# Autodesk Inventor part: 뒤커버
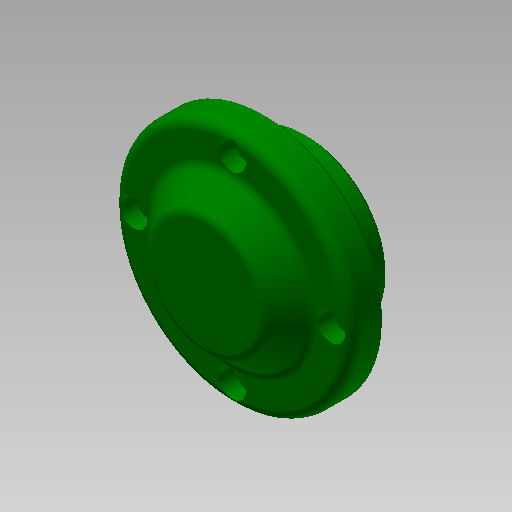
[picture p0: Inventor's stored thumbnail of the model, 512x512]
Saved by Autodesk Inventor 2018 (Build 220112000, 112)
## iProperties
Created: 2017-08
Part Number: 뒤커버
Material: 알루미늄 6061
Document SubType Name: Modeling
Designer: mduedu
Density: 2.71 g/cm^3
Appearance: 알루미늄 - 평지
Author: mduedu
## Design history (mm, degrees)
sketch "스케치1"
  geometry: C1 r 35 at (0, 0); 1 further point
  constraints: 1 centre point, 1 coincident
  dimensions: "d0" = 70 diameter of C1
extrude "돌출1" new body sketch "스케치1" distance "d1" = 10; taper "d2" = 0 deg
sketch "스케치2"
  geometry: C1 r 24 at (0, 0); 1 further point
  constraints: 1 centre point, 1 coincident
  dimensions: "d3" = 48 diameter of C1
node "작업 평면1"
sketch "스케치3"
  geometry: C1 r 17 at (0, 0); 1 further point
  constraints: 1 centre point, 1 coincident
  dimensions: "d5" = 34 diameter of C1
feature "로프트1" sketch "스케치3" dims "d6" = 0, "d7" = 90 deg, "d8" = 0, "d9" = 90 deg
sketch "스케치4"
  geometry: C1 r 24 at (0, 0) reference; 1 further point
extrude "돌출2" join sketch "스케치4" distance "d10" = 12; taper "d11" = 0 deg
hole "구멍1" diameter "d14" = 40; stored, may be unused: countersink angle "d18" = 90 deg, drill point angle "d20" = 0 deg; dims "d15" = 6, "d16" = 4, "d17" = 2, "d19" = 12, "d64" = 10, "d65" = 10
hole "구멍2" diameter "d23" = 36; stored, may be unused: countersink angle "d27" = 90 deg, drill point angle "d29" = 0 deg; dims "d24" = 6, "d25" = 4, "d26" = 2, "d28" = 8, "d62" = 10, "d63" = 10
chamfer "모따기1" distance "d39" = 1; stored, may be unused: second distance "d40" = 2, angle "d41" = 45 deg
fillet "모깎기1" dims "d42" = 0.3
fillet "모깎기2" dims "d43" = 3
sketch "스케치5" dims "d44" = 58
  geometry: 6 further points
  constraints: 2 vertical alignment, 1 coincident, 7 other
  dimensions: "d47" = 360 deg dimension on point (0, 0) point (0, 29) (derived)
sketch "스케치6"
  geometry: 4 further points
  constraints: 4 other
hole "구멍4" sketch "스케치6" at (0, 29), (-29, 0), (29, 0), (0, -29) diameter "d49" = 4.5; stored, may be unused: countersink angle "d53" = 90 deg, drill point angle "d55" = 0 deg; dims "d50" = 6, "d51" = 8, "d52" = 4.6, "d54" = 8
fillet "모깎기3" dims "d56" = 3
fillet "모깎기4" dims "d57" = 3
fillet "모깎기5" dims "d58" = 3
chamfer "모따기2" distance "d59" = 1; stored, may be unused: second distance "d60" = 2, angle "d61" = 45 deg
node "솔리드1"
other parameters: "d4" = 8
